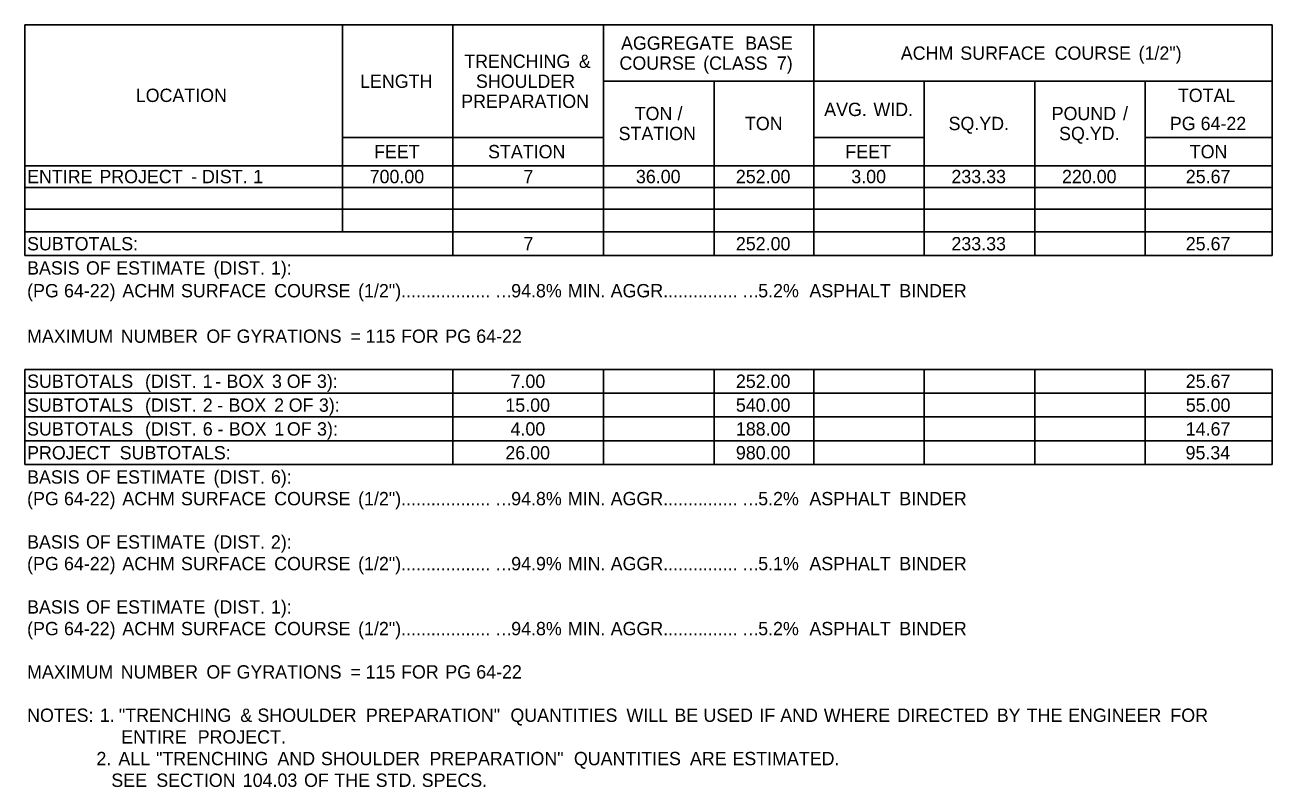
# Model space of a CAD drawing. Extents: x 542596 to 1930787, y -1948294 to 596640.
# Drawn here: x 555684 to 556245, y -1946874 to -1946531 of the extents above; entities that cross this region are included whole.
import ezdxf

# ---------------------------------------------------------------- set-up
doc = ezdxf.new("R2010")
doc.units = 0
doc.layers.add('Default', color=7, linetype='Continuous')

msp = doc.modelspace()

# ---------------------------------------------------------------- linework, layer by layer
at = {"layer": 'Default'}
for p, q in [((555683.57, -1946531.32), (556244.68, -1946531.32)), ((555683.57, -1946635.16), (555683.57, -1946531.32)), ((555826.41, -1946624.44), (555826.41, -1946531.32)), ((555876.13, -1946635.16), (555876.13, -1946531.32)), ((555943.89, -1946635.16), (555943.89, -1946531.32)), ((556038.47, -1946635.16), (556038.47, -1946531.32)), ((556244.68, -1946635.16), (556244.68, -1946531.32)), ((555943.89, -1946556.67), (556244.68, -1946556.67)), ((555993.62, -1946635.16), (555993.62, -1946556.67)), ((556088.19, -1946635.16), (556088.19, -1946556.67)), ((556137.92, -1946635.16), (556137.92, -1946556.67)), ((556187.64, -1946635.16), (556187.64, -1946556.67)), ((555826.41, -1946582.02), (555943.89, -1946582.02)), ((555876.13, -1946635.16), (555876.13, -1946582.02)), ((556038.47, -1946582.02), (556088.19, -1946582.02)), ((556038.47, -1946594.7), (556038.47, -1946582.02)), ((556088.19, -1946624.44), (556088.19, -1946582.02)), ((556187.64, -1946582.02), (556244.68, -1946582.02)), ((555683.57, -1946594.7), (555943.89, -1946594.7)), ((555826.41, -1946624.44), (555826.41, -1946594.7)), ((555943.89, -1946594.7), (556088.19, -1946594.7)), ((555943.89, -1946604.45), (555943.89, -1946594.7)), ((555993.62, -1946624.44), (555993.62, -1946594.7)), ((556088.19, -1946594.7), (556244.68, -1946594.7)), ((556137.92, -1946624.44), (556137.92, -1946594.7)), ((555683.57, -1946604.45), (556244.68, -1946604.45)), ((555683.57, -1946614.2), (556244.68, -1946614.2)), ((555943.89, -1946635.16), (555943.89, -1946614.2)), ((555683.57, -1946624.44), (556187.64, -1946624.44)), ((555683.57, -1946624.44), (556244.68, -1946624.44)), ((556187.64, -1946624.44), (556244.68, -1946624.44)), ((556187.64, -1946635.16), (556187.64, -1946624.44)), ((555683.57, -1946635.16), (556244.68, -1946635.16)), ((555683.57, -1946686.35), (556244.68, -1946686.35)), ((555683.57, -1946686.35), (556244.68, -1946686.35)), ((555683.57, -1946729.25), (555683.57, -1946686.35)), ((555876.13, -1946729.25), (555876.13, -1946686.35)), ((555876.13, -1946729.25), (555876.13, -1946686.35)), ((555943.89, -1946729.25), (555943.89, -1946686.35)), ((555943.89, -1946729.25), (555943.89, -1946686.35)), ((555993.62, -1946729.25), (555993.62, -1946686.35)), ((556038.47, -1946729.25), (556038.47, -1946686.35)), ((556088.19, -1946729.25), (556088.19, -1946686.35)), ((556137.92, -1946729.25), (556137.92, -1946686.35)), ((556187.64, -1946729.25), (556187.64, -1946686.35)), ((556244.68, -1946729.25), (556244.68, -1946686.35)), ((555683.57, -1946697.07), (556038.47, -1946697.07)), ((556038.47, -1946697.07), (556187.64, -1946697.07)), ((556187.64, -1946697.07), (556244.68, -1946697.07)), ((556187.64, -1946729.25), (556187.64, -1946697.07)), ((555683.57, -1946707.8), (556038.47, -1946707.8)), ((556038.47, -1946707.8), (556187.64, -1946707.8)), ((556038.47, -1946707.8), (556187.64, -1946707.8)), ((556187.64, -1946707.8), (556244.68, -1946707.8)), ((555683.57, -1946718.52), (556038.47, -1946718.52)), ((556038.47, -1946718.52), (556187.64, -1946718.52)), ((556038.47, -1946718.52), (556187.64, -1946718.52)), ((556187.64, -1946718.52), (556244.68, -1946718.52)), ((555683.57, -1946729.25), (556244.68, -1946729.25))]:
    msp.add_line(p, q, dxfattribs=at)

# ---------------------------------------------------------------- texts
for s, p in [('AGGREGATE', (555951.77, -1946542.5)), (' BASE', (556005.39, -1946542.5)), ('ACHM', (556077.64, -1946547)), (' SURFACE', (556102.19, -1946547)), (' COURSE', (556144.63, -1946547)), (' (1/2")', (556182.41, -1946547)), ('TRENCHING', (555881.22, -1946550.67)), (' &', (555930.56, -1946550.67)), ('COURSE', (555951.06, -1946551.5)), (' (CLASS', (555986.51, -1946551.5)), (' 7)', (556019.64, -1946551.5)), ('LENGTH', (555834.36, -1946559.67)), ('SHOULDER', (555886.51, -1946559.67)), ('LOCATION', (555733.43, -1946566.01)), ('TOTAL', (556202.32, -1946566.01)), ('PREPARATION', (555879.84, -1946568.67)), ('AVG.', (556043.18, -1946572.35)), (' WID.', (556063.1, -1946572.35)), ('TON', (555957.91, -1946574.19)), (' /', (555974.94, -1946574.19)), ('POUND', (556145.52, -1946574.19)), (' /', (556175.38, -1946574.19)), ('STATION', (555950.69, -1946583.19)), ('TON', (556007.53, -1946578.69)), ('SQ.YD.', (556099.14, -1946578.69)), ('SQ.YD.', (556148.86, -1946583.19)), ('PG', (556198.69, -1946578.69)), (' 64-22', (556210.3, -1946578.69)), ('FEET', (555840.64, -1946591.36)), ('STATION', (555891.95, -1946591.36)), ('FEET', (556052.7, -1946591.36)), ('TON', (556207.65, -1946591.36)), ('ENTIRE', (555684.54, -1946602.57)), (' PROJECT', (555714.84, -1946602.57)), (' -', (555756.13, -1946602.57)), (' DIST.', (555760.99, -1946602.57)), (' 1', (555784.01, -1946602.57)), ('700.00', (555838.66, -1946602.57)), ('7', (555907.87, -1946602.57)), ('36.00', (555958.47, -1946602.57)), ('252.00', (556003.43, -1946602.57)), ('3.00', (556055.38, -1946602.57)), ('233.33', (556100.43, -1946602.57)), ('220.00', (556150.17, -1946602.57)), ('25.67', (556205.87, -1946602.57)), ('SUBTOTALS:', (555684.54, -1946632.8)), ('7', (555907.87, -1946632.8)), ('252.00', (556003.44, -1946632.8)), ('233.33', (556100.42, -1946632.8)), ('25.67', (556205.86, -1946632.8)), ('BASIS', (555684.54, -1946643.71)), (' OF', (555708.8, -1946643.71)), (' ESTIMATE', (555722.39, -1946643.71)), (' (DIST.', (555766.2, -1946643.71)), (' 1):', (555792.01, -1946643.71)), ('(PG', (555684.54, -1946653.95)), (' 64-22)', (555698.92, -1946653.95)), (' ACHM', (555725.17, -1946653.95)), (' SURFACE', (555751.55, -1946653.95)), (' COURSE', (555793.49, -1946653.95)), (' (1/2")..................', (555831.25, -1946653.95)), ('94.8%', (555902.35, -1946653.95)), (' MIN.', (555925.59, -1946653.95)), (' AGGR...............', (555944.88, -1946653.95)), ('5.2%', (556013.48, -1946653.95)), ('  ASPHALT', (556032.06, -1946653.95)), (' BINDER', (556074.75, -1946653.95)), ('…', (555894.95, -1946653.95)), ('…', (556006.08, -1946653.95)), ('MAXIMUM', (555684.54, -1946674.42)), (' NUMBER', (555724.43, -1946674.42)), (' OF', (555762.98, -1946674.42)), (' GYRATIONS', (555776.57, -1946674.42)), (' =', (555827.83, -1946674.42)), (' 115', (555834.59, -1946674.42)), (' FOR', (555850.56, -1946674.42)), (' PG', (555870.48, -1946674.42)), (' 64-22', (555884.39, -1946674.42)), ('SUBTOTALS', (555684.54, -1946694.71)), (' (DIST.', (555735.37, -1946694.71)), (' 1', (555761.34, -1946694.71)), (' BOX', (555772.02, -1946694.71)), (' 3', (555792.51, -1946694.71)), (' OF', (555799.14, -1946694.71)), (' 3):', (555812.72, -1946694.71)), ('7.00', (555902.06, -1946694.71)), ('252.00', (556003.44, -1946694.71)), ('25.67', (556205.86, -1946694.71)), (' -', (555766.97, -1946694.71)), ('SUBTOTALS', (555684.54, -1946705.44)), (' (DIST.', (555735.37, -1946705.44)), (' 2', (555761.34, -1946705.44)), (' BOX', (555772.96, -1946705.44)), (' 2', (555793.45, -1946705.44)), (' OF', (555800.02, -1946705.44)), (' 3):', (555813.6, -1946705.44)), ('15.00', (555899.73, -1946705.44)), ('540.00', (556003.44, -1946705.44)), ('55.00', (556205.88, -1946705.44)), (' -', (555767.9, -1946705.44)), ('SUBTOTALS', (555684.54, -1946716.16)), (' (DIST.', (555735.37, -1946716.16)), (' 6', (555761.34, -1946716.16)), (' BOX', (555773.08, -1946716.16)), (' 1', (555793.57, -1946716.16)), (' OF', (555799.2, -1946716.16)), (' 3):', (555812.78, -1946716.16)), ('4.00', (555902.06, -1946716.16)), ('188.00', (556003.44, -1946716.16)), ('14.67', (556205.86, -1946716.16)), (' -', (555768.03, -1946716.16)), ('PROJECT', (555684.54, -1946726.89)), (' SUBTOTALS:', (555723.97, -1946726.89)), ('26.00', (555899.73, -1946726.89)), ('980.00', (556003.44, -1946726.89)), ('95.34', (556205.77, -1946726.89)), ('BASIS', (555684.54, -1946737.8)), (' OF', (555708.8, -1946737.8)), (' ESTIMATE', (555722.39, -1946737.8)), (' (DIST.', (555766.2, -1946737.8)), (' 6):', (555792.01, -1946737.8)), ('(PG', (555684.54, -1946747.55)), (' 64-22)', (555698.92, -1946747.55)), (' ACHM', (555725.17, -1946747.55)), (' SURFACE', (555751.55, -1946747.55)), (' COURSE', (555793.49, -1946747.55)), (' (1/2")..................', (555831.25, -1946747.55)), ('94.8%', (555902.35, -1946747.55)), (' MIN.', (555925.59, -1946747.55)), (' AGGR...............', (555944.88, -1946747.55)), ('5.2%', (556013.48, -1946747.55)), ('  ASPHALT', (556032.06, -1946747.55)), (' BINDER', (556074.75, -1946747.55)), ('…', (555894.95, -1946747.55)), ('…', (556006.08, -1946747.55)), ('BASIS', (555684.54, -1946767.05)), (' OF', (555708.8, -1946767.05)), (' ESTIMATE', (555722.39, -1946767.05)), (' (DIST.', (555766.2, -1946767.05)), (' 2):', (555792.01, -1946767.05)), ('(PG', (555684.54, -1946776.8)), (' 64-22)', (555698.92, -1946776.8)), (' ACHM', (555725.17, -1946776.8)), (' SURFACE', (555751.55, -1946776.8)), (' COURSE', (555793.49, -1946776.8)), (' (1/2")..................', (555831.25, -1946776.8)), ('94.9%', (555902.35, -1946776.8)), (' MIN.', (555925.59, -1946776.8)), (' AGGR...............', (555944.88, -1946776.8)), ('5.1%', (556013.48, -1946776.8)), ('  ASPHALT', (556032.06, -1946776.8)), (' BINDER', (556074.75, -1946776.8)), ('…', (555894.95, -1946776.8)), ('…', (556006.08, -1946776.8)), ('BASIS', (555684.54, -1946796.3)), (' OF', (555708.8, -1946796.3)), (' ESTIMATE', (555722.39, -1946796.3)), (' (DIST.', (555766.2, -1946796.3)), (' 1):', (555792.01, -1946796.3)), ('(PG', (555684.54, -1946806.05)), (' 64-22)', (555698.92, -1946806.05)), (' ACHM', (555725.17, -1946806.05)), (' SURFACE', (555751.55, -1946806.05)), (' COURSE', (555793.49, -1946806.05)), (' (1/2")..................', (555831.25, -1946806.05)), ('94.8%', (555902.35, -1946806.05)), (' MIN.', (555925.59, -1946806.05)), (' AGGR...............', (555944.88, -1946806.05)), ('5.2%', (556013.48, -1946806.05)), ('  ASPHALT', (556032.06, -1946806.05)), (' BINDER', (556074.75, -1946806.05)), ('…', (555894.95, -1946806.05)), ('…', (556006.08, -1946806.05)), ('MAXIMUM', (555684.54, -1946825.55)), (' NUMBER', (555724.43, -1946825.55)), (' OF', (555762.98, -1946825.55)), (' GYRATIONS', (555776.57, -1946825.55)), (' =', (555827.83, -1946825.55)), (' 115', (555834.59, -1946825.55)), (' FOR', (555850.56, -1946825.55)), (' PG', (555870.48, -1946825.55)), (' 64-22', (555884.39, -1946825.55)), ('NOTES:', (555684.54, -1946845.05)), (' 1.', (555715.02, -1946845.05)), (' "TRENCHING', (555723.61, -1946845.05)), (' &', (555778.23, -1946845.05)), (' SHOULDER', (555785.95, -1946845.05)), (' PREPARATION"', (555834.75, -1946845.05)), (' QUANTITIES', (555899.77, -1946845.05)), (' WILL', (555951.96, -1946845.05)), (' BE', (555973.55, -1946845.05)), (' USED', (555986.62, -1946845.05)), (' IF', (556011.8, -1946845.05)), (' AND', (556021.19, -1946845.05)), (' WHERE', (556040.77, -1946845.05)), (' DIRECTED', (556073.86, -1946845.05)), (' BY', (556118.59, -1946845.05)), (' THE', (556132.04, -1946845.05)), (' ENGINEER', (556150.69, -1946845.05)), (' FOR', (556196.7, -1946845.05)), ('                   ENTIRE', (555684.54, -1946854.8)), (' PROJECT.', (555759.07, -1946854.8)), ('              2.', (555684.54, -1946864.55)), (' ALL', (555723.39, -1946864.55)), (' "TRENCHING', (555740.33, -1946864.55)), (' AND', (555794.95, -1946864.55)), (' SHOULDER', (555814.53, -1946864.55)), (' PREPARATION"', (555863.33, -1946864.55)), (' QUANTITIES', (555928.34, -1946864.55)), (' ARE', (555980.54, -1946864.55)), (' ESTIMATED.', (555999.66, -1946864.55)), ('                 SEE', (555684.54, -1946874.3)), (' SECTION', (555740.45, -1946874.3)), (' 104.03', (555779.35, -1946874.3)), (' OF', (555806.93, -1946874.3)), (' THE', (555820.52, -1946874.3)), (' STD.', (555839.17, -1946874.3)), (' SPECS.', (555859.86, -1946874.3))]:
    msp.add_text(s, height=6, dxfattribs=at).set_placement(p)

doc.saveas('drawing.dxf')
